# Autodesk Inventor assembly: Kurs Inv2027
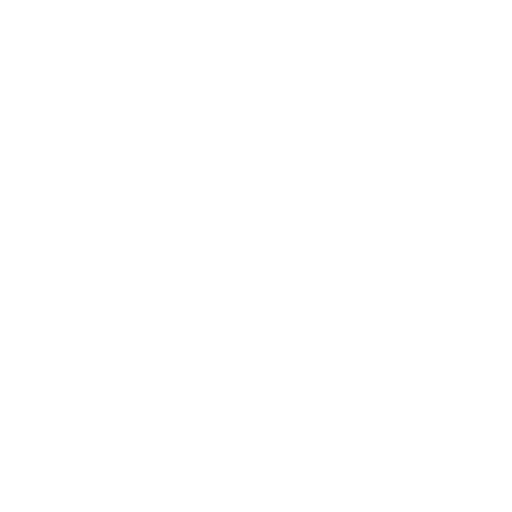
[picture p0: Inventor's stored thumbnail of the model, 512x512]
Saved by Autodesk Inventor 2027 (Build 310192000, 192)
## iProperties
Created: 2010-03
Part Number: Kurs Inv2027
Document SubType Name: Assembly
Designer: Johan Wedeen
Manufacturer: Standard
Standards Organization: Custom
Author: Johan Wedeen
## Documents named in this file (1)
- C:\Users\Public\Documents\Autodesk\Inventor 2027\Templates\InventorKurs\Kurs Inv2027.iam
